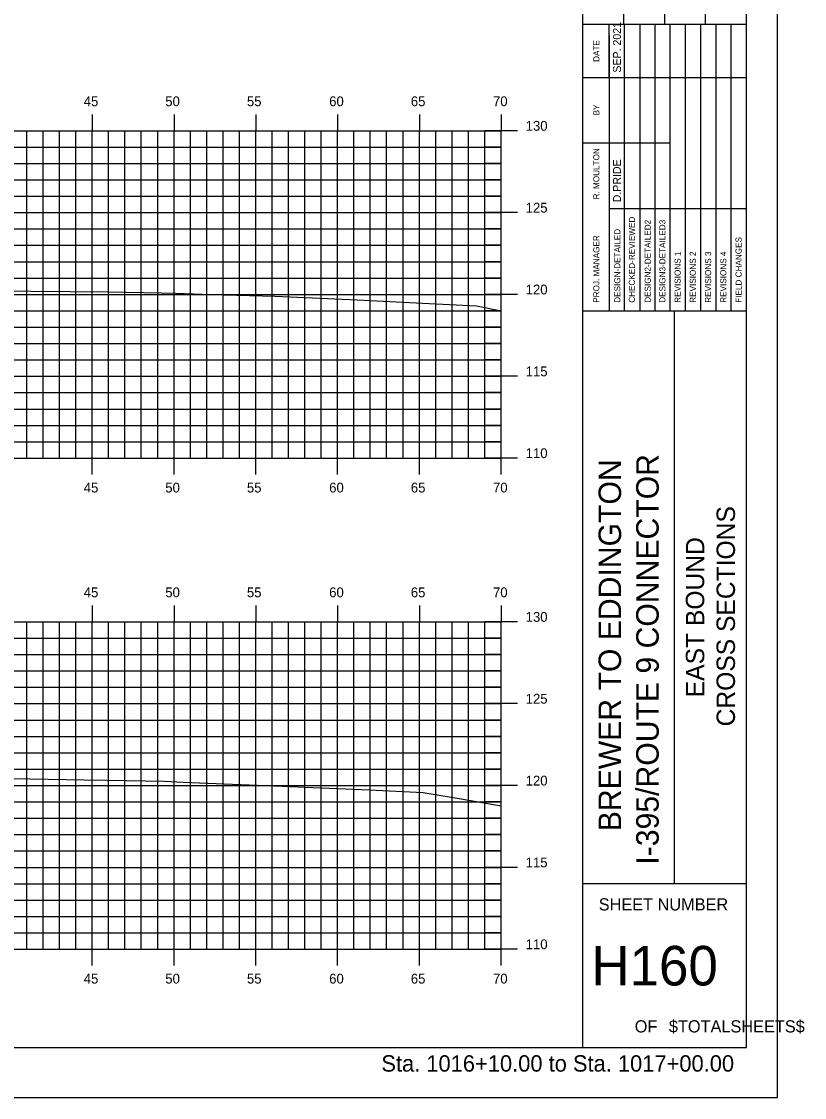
# Model space of a CAD drawing. Extents: x 853291 to 853462, y 365624 to 365734.
# Drawn here: x 853414.5 to 853462.4, y 365624 to 365689.7 of the extents above; entities that cross this region are included whole.
import ezdxf

# ---------------------------------------------------------------- set-up
doc = ezdxf.new("R2010")
doc.units = 0
for name, color, linetype in [('BORDER', 7, 'Continuous'), ('H_V ANNOTATION', 7, 'Continuous'), ('M_Roadway_Centerline', 7, 'Continuous'), ('MAJOR', 7, 'Continuous'), ('MINOR', 7, 'Continuous'), ('PLOT BOUNDARY', 7, 'Continuous'), ('S_Roadway_Centerline', 7, 'Continuous')]:
    doc.layers.add(name, color=color, linetype=linetype)

msp = doc.modelspace()

# ---------------------------------------------------------------- linework, layer by layer
at = {"layer": 'BORDER'}
for p, q in [((853448.818, 365627.027), (853448.818, 365732.027)), ((853451.318, 365689.53), (853451.318, 365698.177)), ((853453.818, 365689.53), (853453.818, 365698.177)), ((853456.318, 365689.53), (853456.318, 365698.177)), ((853448.818, 365689.53), (853458.818, 365689.53)), ((853448.818, 365672.03), (853458.818, 365672.03)), ((853454.409, 365637.03), (853454.409, 365672.03)), ((853448.818, 365637.03), (853458.818, 365637.03))]:
    msp.add_line(p, q, dxfattribs=at)
msp.add_lwpolyline([(853298.818, 365627.027), (853458.818, 365627.027), (853458.818, 365732.027), (853298.818, 365732.027)], close=True, dxfattribs=at)
for points in [[(853450.433, 365686.28), (853450.433, 365689.53)], [(853451.366, 365672.033), (853451.366, 365689.53)], [(853452.297, 365689.53), (853452.297, 365672.033)], [(853453.229, 365672.033), (853453.229, 365689.53)], [(853454.161, 365672.033), (853454.161, 365689.53)], [(853455.092, 365672.033), (853455.092, 365689.53)], [(853456.024, 365672.033), (853456.024, 365689.53)], [(853456.956, 365672.033), (853456.956, 365689.53)], [(853457.887, 365672.033), (853457.887, 365689.53)], [(853450.434, 365672.033), (853450.434, 365688.824)], [(853448.818, 365686.28), (853458.818, 365686.28)], [(853448.818, 365682.28), (853450.434, 365682.28)], [(853450.433, 365682.28), (853454.16, 365682.28)], [(853450.433, 365678.28), (853458.818, 365678.28)]]:
    msp.add_lwpolyline(points, dxfattribs=at)
at = {"layer": 'MAJOR'}
for p, q in [((853418.818, 365684.029), (853418.818, 365683.027)), ((853423.818, 365684.029), (853423.818, 365683.027)), ((853428.818, 365684.029), (853428.818, 365683.027)), ((853433.818, 365684.029), (853433.818, 365683.027)), ((853438.818, 365684.029), (853438.818, 365683.027)), ((853443.818, 365684.029), (853443.818, 365683.027)), ((853303.818, 365683.027), (853443.818, 365683.027)), ((853303.818, 365683.027), (853443.818, 365683.027)), ((853418.818, 365663.027), (853418.818, 365683.027)), ((853423.818, 365663.027), (853423.818, 365683.027)), ((853428.818, 365663.027), (853428.818, 365683.027)), ((853433.818, 365663.027), (853433.818, 365683.027)), ((853438.818, 365663.027), (853438.818, 365683.027)), ((853444.82, 365683.027), (853442.816, 365683.027)), ((853443.818, 365663.027), (853443.818, 365683.027)), ((853443.818, 365663.027), (853443.818, 365683.027)), ((853303.818, 365678.027), (853443.818, 365678.027)), ((853444.82, 365678.027), (853442.816, 365678.027)), ((853303.818, 365673.027), (853443.818, 365673.027)), ((853444.82, 365673.027), (853442.816, 365673.027)), ((853303.818, 365668.027), (853443.818, 365668.027)), ((853444.82, 365668.027), (853442.816, 365668.027)), ((853303.818, 365663.027), (853443.818, 365663.027)), ((853303.818, 365663.027), (853443.818, 365663.027)), ((853418.818, 365662.025), (853418.818, 365663.027)), ((853423.818, 365662.025), (853423.818, 365663.027)), ((853428.818, 365662.025), (853428.818, 365663.027)), ((853433.818, 365662.025), (853433.818, 365663.027)), ((853438.818, 365662.025), (853438.818, 365663.027)), ((853444.82, 365663.027), (853442.816, 365663.027)), ((853443.818, 365662.025), (853443.818, 365663.027)), ((853418.818, 365654.029), (853418.818, 365653.027)), ((853423.818, 365654.029), (853423.818, 365653.027)), ((853428.818, 365654.029), (853428.818, 365653.027)), ((853433.818, 365654.029), (853433.818, 365653.027)), ((853438.818, 365654.029), (853438.818, 365653.027)), ((853443.818, 365654.029), (853443.818, 365653.027)), ((853303.818, 365653.027), (853443.818, 365653.027)), ((853303.818, 365653.027), (853443.818, 365653.027)), ((853418.818, 365633.027), (853418.818, 365653.027)), ((853423.818, 365633.027), (853423.818, 365653.027)), ((853428.818, 365633.027), (853428.818, 365653.027)), ((853433.818, 365633.027), (853433.818, 365653.027)), ((853438.818, 365633.027), (853438.818, 365653.027)), ((853444.82, 365653.027), (853442.816, 365653.027)), ((853443.818, 365633.027), (853443.818, 365653.027)), ((853443.818, 365633.027), (853443.818, 365653.027)), ((853303.818, 365648.027), (853443.818, 365648.027)), ((853444.82, 365648.027), (853442.816, 365648.027)), ((853303.818, 365643.027), (853443.818, 365643.027)), ((853444.82, 365643.027), (853442.816, 365643.027)), ((853303.818, 365638.027), (853443.818, 365638.027)), ((853444.82, 365638.027), (853442.816, 365638.027)), ((853303.818, 365633.027), (853443.818, 365633.027)), ((853303.818, 365633.027), (853443.818, 365633.027)), ((853418.818, 365632.025), (853418.818, 365633.027)), ((853423.818, 365632.025), (853423.818, 365633.027)), ((853428.818, 365632.025), (853428.818, 365633.027)), ((853433.818, 365632.025), (853433.818, 365633.027)), ((853438.818, 365632.025), (853438.818, 365633.027)), ((853444.82, 365633.027), (853442.816, 365633.027)), ((853443.818, 365632.025), (853443.818, 365633.027))]:
    msp.add_line(p, q, dxfattribs=at)
at = {"layer": 'MINOR'}
for p, q in [((853414.818, 365663.027), (853414.818, 365683.027)), ((853415.818, 365663.027), (853415.818, 365683.027)), ((853416.818, 365663.027), (853416.818, 365683.027)), ((853417.818, 365663.027), (853417.818, 365683.027)), ((853419.818, 365663.027), (853419.818, 365683.027)), ((853420.818, 365663.027), (853420.818, 365683.027)), ((853421.818, 365663.027), (853421.818, 365683.027)), ((853422.818, 365663.027), (853422.818, 365683.027)), ((853424.818, 365663.027), (853424.818, 365683.027)), ((853425.818, 365663.027), (853425.818, 365683.027)), ((853426.818, 365663.027), (853426.818, 365683.027)), ((853427.818, 365663.027), (853427.818, 365683.027)), ((853429.818, 365663.027), (853429.818, 365683.027)), ((853430.818, 365663.027), (853430.818, 365683.027)), ((853431.818, 365663.027), (853431.818, 365683.027)), ((853432.818, 365663.027), (853432.818, 365683.027)), ((853434.818, 365663.027), (853434.818, 365683.027)), ((853435.818, 365663.027), (853435.818, 365683.027)), ((853436.818, 365663.027), (853436.818, 365683.027)), ((853437.818, 365663.027), (853437.818, 365683.027)), ((853439.818, 365663.027), (853439.818, 365683.027)), ((853440.818, 365663.027), (853440.818, 365683.027)), ((853441.818, 365663.027), (853441.818, 365683.027)), ((853442.818, 365663.027), (853442.818, 365683.027)), ((853303.818, 365682.027), (853443.818, 365682.027)), ((853443.818, 365682.027), (853442.816, 365682.027)), ((853303.818, 365681.027), (853443.818, 365681.027)), ((853443.818, 365681.027), (853442.816, 365681.027)), ((853303.818, 365680.027), (853443.818, 365680.027)), ((853443.818, 365680.027), (853442.816, 365680.027)), ((853303.818, 365679.027), (853443.818, 365679.027)), ((853443.818, 365679.027), (853442.816, 365679.027)), ((853303.818, 365677.027), (853443.818, 365677.027)), ((853443.818, 365677.027), (853442.816, 365677.027)), ((853303.818, 365676.027), (853443.818, 365676.027)), ((853443.818, 365676.027), (853442.816, 365676.027)), ((853303.818, 365675.027), (853443.818, 365675.027)), ((853443.818, 365675.027), (853442.816, 365675.027)), ((853303.818, 365674.027), (853443.818, 365674.027)), ((853443.818, 365674.027), (853442.816, 365674.027)), ((853303.818, 365672.027), (853443.818, 365672.027)), ((853443.818, 365672.027), (853442.816, 365672.027)), ((853303.818, 365671.027), (853443.818, 365671.027)), ((853443.818, 365671.027), (853442.816, 365671.027)), ((853303.818, 365670.027), (853443.818, 365670.027)), ((853443.818, 365670.027), (853442.816, 365670.027)), ((853303.818, 365669.027), (853443.818, 365669.027)), ((853443.818, 365669.027), (853442.816, 365669.027)), ((853303.818, 365667.027), (853443.818, 365667.027)), ((853443.818, 365667.027), (853442.816, 365667.027)), ((853303.818, 365666.027), (853443.818, 365666.027)), ((853443.818, 365666.027), (853442.816, 365666.027)), ((853303.818, 365665.027), (853443.818, 365665.027)), ((853443.818, 365665.027), (853442.816, 365665.027)), ((853303.818, 365664.027), (853443.818, 365664.027)), ((853443.818, 365664.027), (853442.816, 365664.027)), ((853414.818, 365633.027), (853414.818, 365653.027)), ((853415.818, 365633.027), (853415.818, 365653.027)), ((853416.818, 365633.027), (853416.818, 365653.027)), ((853417.818, 365633.027), (853417.818, 365653.027)), ((853419.818, 365633.027), (853419.818, 365653.027)), ((853420.818, 365633.027), (853420.818, 365653.027)), ((853421.818, 365633.027), (853421.818, 365653.027)), ((853422.818, 365633.027), (853422.818, 365653.027)), ((853424.818, 365633.027), (853424.818, 365653.027)), ((853425.818, 365633.027), (853425.818, 365653.027)), ((853426.818, 365633.027), (853426.818, 365653.027)), ((853427.818, 365633.027), (853427.818, 365653.027)), ((853429.818, 365633.027), (853429.818, 365653.027)), ((853430.818, 365633.027), (853430.818, 365653.027)), ((853431.818, 365633.027), (853431.818, 365653.027)), ((853432.818, 365633.027), (853432.818, 365653.027)), ((853434.818, 365633.027), (853434.818, 365653.027)), ((853435.818, 365633.027), (853435.818, 365653.027)), ((853436.818, 365633.027), (853436.818, 365653.027)), ((853437.818, 365633.027), (853437.818, 365653.027)), ((853439.818, 365633.027), (853439.818, 365653.027)), ((853440.818, 365633.027), (853440.818, 365653.027)), ((853441.818, 365633.027), (853441.818, 365653.027)), ((853442.818, 365633.027), (853442.818, 365653.027)), ((853303.818, 365652.027), (853443.818, 365652.027)), ((853443.818, 365652.027), (853442.816, 365652.027)), ((853303.818, 365651.027), (853443.818, 365651.027)), ((853443.818, 365651.027), (853442.816, 365651.027)), ((853303.818, 365650.027), (853443.818, 365650.027)), ((853443.818, 365650.027), (853442.816, 365650.027)), ((853303.818, 365649.027), (853443.818, 365649.027)), ((853443.818, 365649.027), (853442.816, 365649.027)), ((853303.818, 365647.027), (853443.818, 365647.027)), ((853443.818, 365647.027), (853442.816, 365647.027)), ((853303.818, 365646.027), (853443.818, 365646.027)), ((853443.818, 365646.027), (853442.816, 365646.027)), ((853303.818, 365645.027), (853443.818, 365645.027)), ((853443.818, 365645.027), (853442.816, 365645.027)), ((853303.818, 365644.027), (853443.818, 365644.027)), ((853443.818, 365644.027), (853442.816, 365644.027)), ((853303.818, 365642.027), (853443.818, 365642.027)), ((853443.818, 365642.027), (853442.816, 365642.027)), ((853303.818, 365641.027), (853443.818, 365641.027)), ((853443.818, 365641.027), (853442.816, 365641.027)), ((853303.818, 365640.027), (853443.818, 365640.027)), ((853443.818, 365640.027), (853442.816, 365640.027)), ((853303.818, 365639.027), (853443.818, 365639.027)), ((853443.818, 365639.027), (853442.816, 365639.027)), ((853303.818, 365637.027), (853443.818, 365637.027)), ((853443.818, 365637.027), (853442.816, 365637.027)), ((853303.818, 365636.027), (853443.818, 365636.027)), ((853443.818, 365636.027), (853442.816, 365636.027)), ((853303.818, 365635.027), (853443.818, 365635.027)), ((853443.818, 365635.027), (853442.816, 365635.027)), ((853303.818, 365634.027), (853443.818, 365634.027)), ((853443.818, 365634.027), (853442.816, 365634.027))]:
    msp.add_line(p, q, dxfattribs=at)
at = {"layer": 'PLOT BOUNDARY'}
msp.add_lwpolyline([(853290.725, 365623.968), (853460.725, 365623.968), (853460.725, 365733.968), (853290.725, 365733.968)], close=True, dxfattribs=at)
at = {"layer": 'S_Roadway_Centerline'}
for points in [[(853358.875, 365670.837), (853363.418, 365671.415), (853366.332, 365671.608), (853370.17, 365671.984), (853376.668, 365672.507), (853376.793, 365672.501), (853385.888, 365672.827), (853387.116, 365672.883), (853389.357, 365673.032), (853389.951, 365673.032), (853397.371, 365673.197), (853399.332, 365673.233), (853405.546, 365673.305), (853419.84, 365673.18), (853423.032, 365673.134), (853423.924, 365673.108), (853426.083, 365673.03), (853429.997, 365672.918), (853435.022, 365672.7), (853439.425, 365672.472), (853442.303, 365672.336), (853443.818, 365672.022)], [(853359.562, 365641.24), (853378.698, 365642.784), (853379.227, 365642.835), (853379.596, 365642.847), (853384.21, 365642.929), (853389.782, 365643.151), (853391.849, 365643.245), (853395.6, 365643.328), (853398.86, 365643.411), (853408.287, 365643.553), (853418.351, 365643.372), (853419.706, 365643.349), (853423.234, 365643.292), (853424.384, 365643.233), (853430.917, 365642.97), (853432.314, 365642.913), (853435.76, 365642.761), (853439.046, 365642.595), (853441.367, 365642.215), (853443.818, 365641.784)]]:
    msp.add_lwpolyline(points, dxfattribs=at)

# ---------------------------------------------------------------- texts
at = {"layer": 'BORDER'}
for s, height, p in [('SEP. 2021', 0.4845, (853451.141, 365686.575)), ('DATE', 0.3714, (853449.822, 365687.235)), ('BY', 0.3714, (853449.822, 365683.965)), ('R. MOULTON', 0.3727, (853449.822, 365678.832)), ('D.PRIDE', 0.4845, (853451.141, 365678.653)), ('CHECKED-REVIEWED', 0.37275, (853451.999, 365672.518)), ('DESIGN2-DETAILED2', 0.37275, (853452.968, 365672.518)), ('DESIGN3-DETAILED3', 0.37275, (853453.863, 365672.518)), ('DESIGN-DETAILED', 0.37275, (853451.105, 365672.518)), ('PROJ. MANAGER', 0.37275, (853449.822, 365672.518)), ('FIELD CHANGES', 0.37275, (853458.521, 365672.518)), ('REVISIONS 1', 0.37275, (853454.794, 365672.518)), ('REVISIONS 2', 0.37275, (853455.726, 365672.518)), ('REVISIONS 3', 0.37275, (853456.658, 365672.518)), ('REVISIONS 4', 0.37275, (853457.589, 365672.518)), ('I-395/ROUTE 9 CONNECTOR', 1.37787, (853453.453, 365638.192)), ('BREWER TO EDDINGTON', 1.37787, (853451.152, 365640.231)), ('CROSS SECTIONS', 1.125, (853458.115, 365646.638)), ('EAST BOUND', 1.125, (853456.236, 365648.418))]:
    msp.add_text(s, height=height, rotation=90, dxfattribs=at).set_placement(p)
for s, height, p in [('SHEET NUMBER', 0.74527, (853449.784, 365635.393)), ('H160', 2.4194, (853449.334, 365630.809)), ('$TOTALSHEETS$', 0.74527, (853454.075, 365627.94)), ('OF', 0.7453, (853451.985, 365627.94))]:
    msp.add_text(s, height=height, dxfattribs=at).set_placement(p)
at = {"layer": 'H_V ANNOTATION'}
for s, height, p in [('45', 0.6, (853418.296, 365684.527)), ('50', 0.6, (853423.283, 365684.527)), ('55', 0.6, (853428.275, 365684.527)), ('60', 0.6, (853433.304, 365684.527)), ('65', 0.6, (853438.296, 365684.527)), ('70', 0.6, (853443.32, 365684.527)), ('130', 0.6, (853445.318, 365683.027)), ('125', 0.6, (853445.318, 365678.027)), ('120', 0.6, (853445.318, 365673.027)), ('115', 0.6, (853445.318, 365668.027)), ('110', 0.6, (853445.318, 365663.027)), ('45', 0.6, (853418.296, 365660.927)), ('50', 0.6, (853423.283, 365660.927)), ('55', 0.6, (853428.275, 365660.927)), ('60', 0.6, (853433.304, 365660.927)), ('65', 0.6, (853438.296, 365660.927)), ('70', 0.6, (853443.32, 365660.927)), ('45', 0.6, (853418.296, 365654.527)), ('50', 0.6, (853423.283, 365654.527)), ('55', 0.6, (853428.275, 365654.527)), ('60', 0.6, (853433.304, 365654.527)), ('65', 0.6, (853438.296, 365654.527)), ('70', 0.6, (853443.32, 365654.527)), ('130', 0.6, (853445.318, 365653.027)), ('125', 0.6, (853445.318, 365648.027)), ('120', 0.6, (853445.318, 365643.027)), ('115', 0.6, (853445.318, 365638.027)), ('110', 0.6, (853445.318, 365633.027)), ('45', 0.6, (853418.296, 365630.927)), ('50', 0.6, (853423.283, 365630.927)), ('55', 0.6, (853428.275, 365630.927)), ('60', 0.6, (853433.304, 365630.927)), ('65', 0.6, (853438.296, 365630.927)), ('70', 0.6, (853443.32, 365630.927)), ('Sta. 1016+10.00 to Sta. 1017+00.00', 1.0002, (853436.494, 365625.547))]:
    msp.add_text(s, height=height, dxfattribs=at).set_placement(p)
at = {"layer": 'M_Roadway_Centerline'}
for s, p in [('C', (853426.078, 365673.03)), ('L', (853426.083, 365673.023))]:
    msp.add_text(s, height=0.0146, dxfattribs=at).set_placement(p)

doc.saveas('drawing.dxf')
